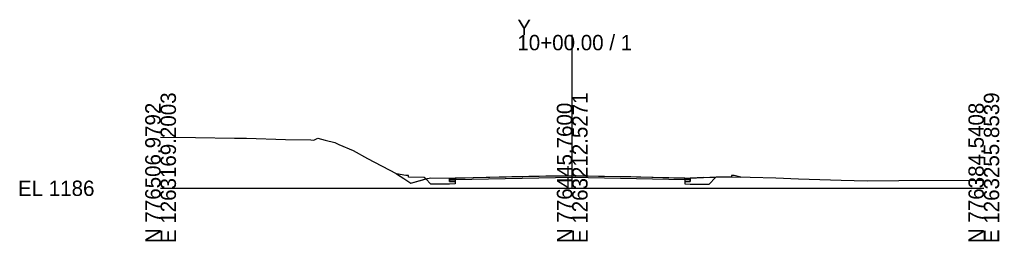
# Model space of a CAD drawing. Extents: x -51 to 1263719, y -10 to 776845.
# Drawn here: x -25.7 to 152.8, y -9.7 to 30.8 of the extents above; entities that cross this region are included whole.
import ezdxf

# ---------------------------------------------------------------- set-up
doc = ezdxf.new("R2010")
doc.units = 0
for name, color, linetype in [('Exist Cross Section Cell', 7, 'Continuous'), ('Exist XS Ground Line', 7, 'Continuous'), ('Prop XS Earthwork Shape', 7, 'Continuous')]:
    doc.layers.add(name, color=color, linetype=linetype)

msp = doc.modelspace()

# ---------------------------------------------------------------- linework, layer by layer
at = {"layer": 'Exist Cross Section Cell'}
for p, q in [((75, 0), (75, 27.97)), ((0, 0), (75, 0)), ((75, 0), (150, 0))]:
    msp.add_line(p, q, dxfattribs=at)
at = {"layer": 'Exist XS Ground Line'}
msp.add_lwpolyline([(0, 9.32), (6.36, 9.28), (13.44, 9.14), (14.24, 9.14), (15.64, 9.12), (22.75, 8.92), (27.38, 8.81), (27.91, 8.8), (28.65, 9.12), (29.96, 8.78), (31.73, 8.32), (32.48, 7.98), (35.09, 6.87), (37.71, 5.46), (42.93, 2.68), (44.3, 1.78), (45.6, 0.96), (48.61, 1.78), (49.22, 1.92), (52.67, 1.83), (57.03, 1.94), (63.98, 2.16), (70.19, 2.25), (74.85, 2.26), (84.73, 2.14), (85.71, 2.12), (87.53, 2.08), (96.51, 1.82), (101.26, 2.09), (102.1, 2.11), (107.45, 2.01), (112.09, 1.92), (116.25, 1.75), (124.02, 1.47), (128.76, 1.37), (134.5, 1.4), (148.93, 1.45), (150, 1.46)], dxfattribs=at)
at = {"layer": 'Prop XS Earthwork Shape'}
for points in [[(48.3, 1.7), (48.05, 1.95), (45.17, 2.01), (45.17, 2.34), (44.67, 2.35), (43.01, 2.63), (44.3, 1.78), (45.6, 0.96)], [(48.3, 1.7), (48.61, 1.78), (49.22, 1.92), (52.67, 1.83), (52.67, 1.58), (52.67, 1.24), (53.67, 1.26), (53.67, 0.8), (52.67, 0.78), (49.22, 0.78)], [(52.67, 1.83), (53.67, 1.85), (53.67, 1.59), (52.67, 1.58)], [(53.96, 1.86), (53.67, 1.85), (53.67, 1.59), (75, 2), (95.51, 1.59), (95.51, 1.84), (75, 2.25)], [(53.96, 1.86), (57.03, 1.94), (63.98, 2.16), (70.19, 2.25), (74.85, 2.26), (84.73, 2.14), (85.71, 2.12), (87.53, 2.08), (95.51, 1.84), (75, 2.25)], [(101.13, 1.95), (99.01, 1.9), (99.01, 1.96), (96.51, 1.82), (96.51, 1.57), (96.51, 1.24), (95.51, 1.26), (95.51, 0.8), (96.51, 0.78), (99.97, 0.78)], [(95.51, 1.84), (96.51, 1.82), (96.51, 1.57), (95.51, 1.59)], [(99.01, 1.96), (101.26, 2.09), (102.1, 2.11), (104.01, 2.07), (104.01, 2), (101.13, 1.95), (99.01, 1.9)], [(104.01, 2.07), (105.73, 2.04), (104.51, 2.35), (104.01, 2.34)], [(53.67, 1.59), (53.67, 1.26), (52.67, 1.24), (52.67, 1.58)], [(96.51, 1.24), (96.51, 1.57), (95.51, 1.59), (95.51, 1.26)]]:
    msp.add_lwpolyline(points, close=True, dxfattribs=at)

# ---------------------------------------------------------------- texts
at = {"layer": 'Exist Cross Section Cell'}
for s, p in [('Y', (65, 27.97)), ('10+00.00 / 1', (65, 25.17)), ('EL 1186', (-26, -1.4))]:
    msp.add_text(s, height=2.8, dxfattribs=at).set_placement(p)
for s, p in [('E 1263169.2003', (2.8, -10)), ('E 1263212.5271', (77.8, -10)), ('E 1263255.8539', (152.8, -10)), ('N 776506.9792', (0, -10)), ('N 776445.7600', (75, -10)), ('N 776384.5408', (150, -10))]:
    msp.add_text(s, height=2.8, rotation=90, dxfattribs=at).set_placement(p)

doc.saveas('drawing.dxf')
